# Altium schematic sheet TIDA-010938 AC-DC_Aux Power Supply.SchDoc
size 431 x 279 mm; Date: Not shown in title block; ApprovedBy: Not shown in title block; CheckedBy: Not shown in title block; Author: Not shown in title block; CompanyName: Not shown in title block; Engineer: Not shown in title block; Organization: Not shown in title block; Address1: Not shown in title block; Address2: Not shown in title block; Address3: Not shown in title block; Address4: Not shown in title block; DocumentNumber: 4; Revision: Use project parameter SCH_Rev; SheetNumber: 5; SheetTotal: 11; PageSetup: Record=PageOptions¦CenterHorizontal=True¦CenterVertical=True¦PrintScale=1.00¦XCorrection=1.00¦YCorrection=1.00¦PrintKind=0¦BorderSize=5000000¦LeftOffset=0¦BottomOffset=0¦Orientation=2¦PaperLength=1000¦PaperWidth=1000¦Scale=100¦PaperSource=15¦PrintQuality=600¦MediaType=1¦DitherType=10¦PaperKind=Letter¦PrintScaleMode=1
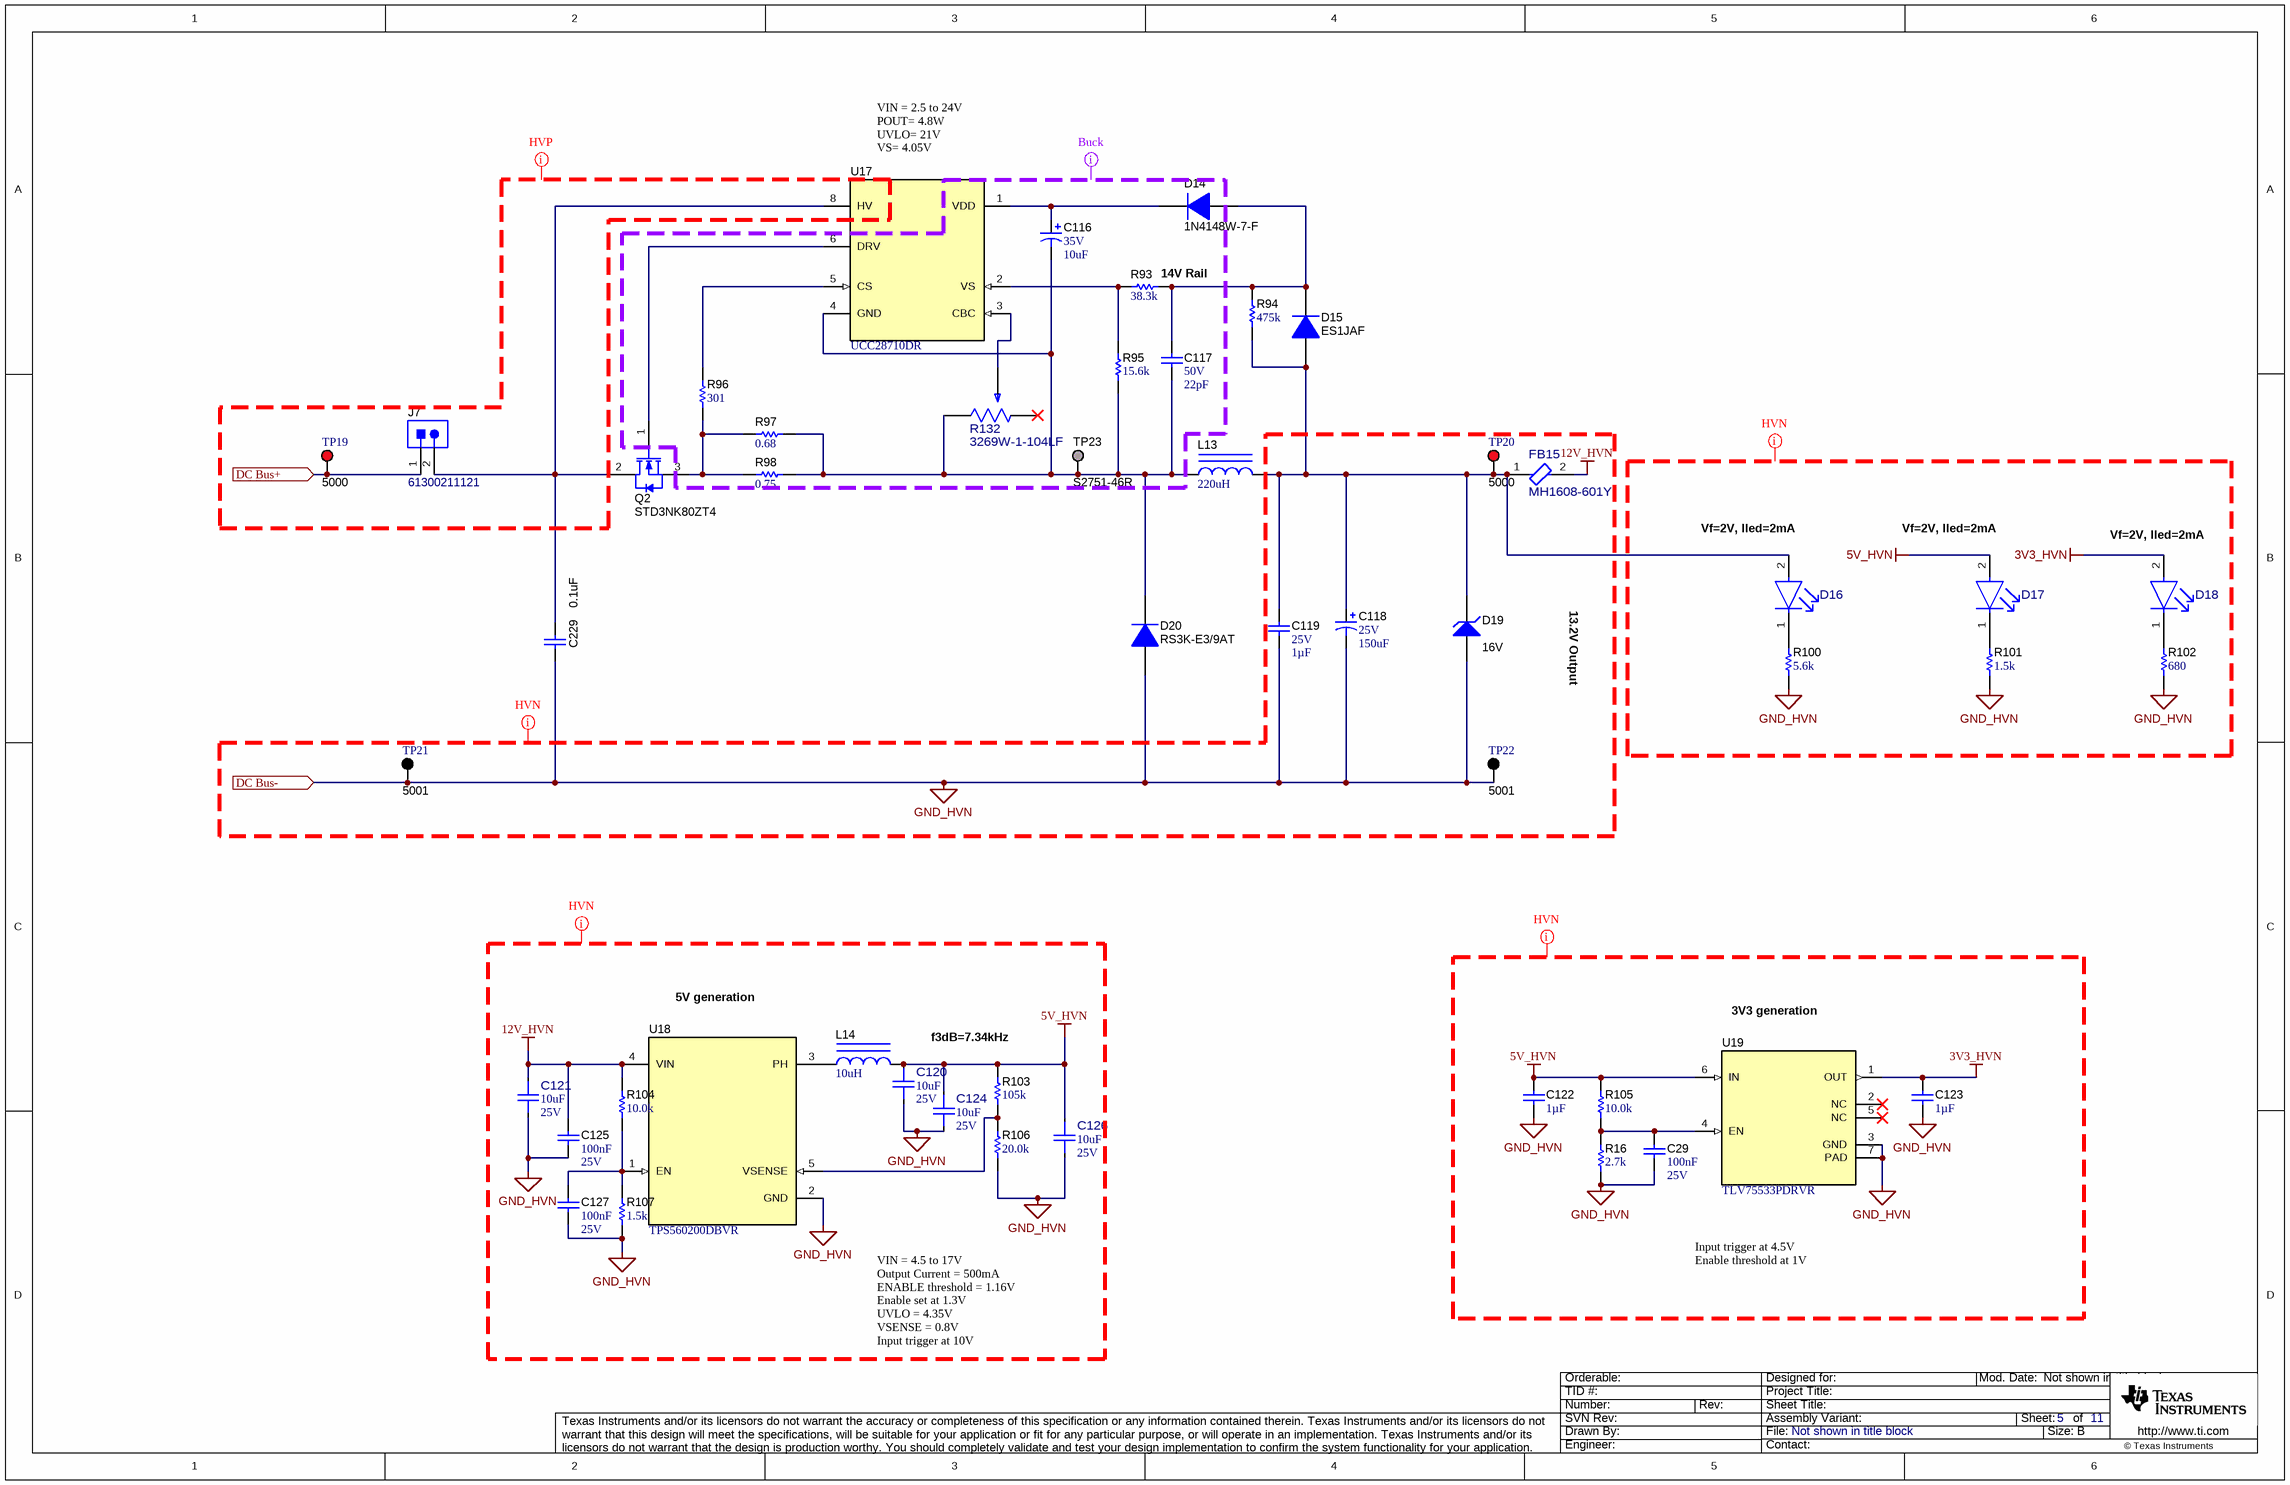
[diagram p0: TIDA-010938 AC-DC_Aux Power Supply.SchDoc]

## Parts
C29  Cap_F: 100nF  VDC_V: 25V  [0603]  (hidden comment: 06033C104JAT2A)
C116  VDC_V: 35V  ValueDisplayed: 10uF  [CAPPR2-5x11]  (hidden comment: UVR1V100MDD1TA)
C117  VDC_V: 50V  ValueDisplayed: 22pF  [0603]  (hidden comment: 06035A220JAT2A)
C118  VDC_V: 25V  ValueDisplayed: 150uF  [FR_630X1120]  (hidden comment: EEU-FR1E151B)
C119  VDC_V: 25V  ValueDisplayed: 1µF  [0603]  (hidden comment: TMK107BJ105KA-T)
C120  ValueDisplayed: 10uF  VDC_V: 25V  [FP-ZRB18AR61E106ME01L_0603-MFG]  (hidden comment: ZRB18AR61E106ME01L)
C121  ValueDisplayed: 10uF  VDC_V: 25V  [FP-ZRB18AR61E106ME01L_0603-MFG]  (hidden comment: ZRB18AR61E106ME01L)
C122  Cap_F: 1µF  [0603]  (hidden comment: 885012206026)
C123  Cap_F: 1µF  [0603]  (hidden comment: 885012206026)
C124  ValueDisplayed: 10uF  VDC_V: 25V  [FP-ZRB18AR61E106ME01L_0603-MFG]  (hidden comment: ZRB18AR61E106ME01L)
C125  Cap_F: 100nF  VDC_V: 25V  [0603]  (hidden comment: 06033C104JAT2A)
C126  ValueDisplayed: 10uF  VDC_V: 25V  [FP-ZRB18AR61E106ME01L_0603-MFG]  (hidden comment: ZRB18AR61E106ME01L)
C127  Cap_F: 100nF  VDC_V: 25V  [0603]  (hidden comment: 06033C104JAT2A)
C229  ValueDisplayed: 0.1uF  [1812_254]  (hidden comment: C1812W104KDRACTU)
D14  1N4148W-7-F  [SOD-123]
D15  ES1JAF  [SMAF]
D16  KG DELLS1.22-JGKH-24  [FP-KG DELLS1.22-JGKH-24_0603-MFG]  (value not drawn)
D17  KG DELLS1.22-JGKH-24  [FP-KG DELLS1.22-JGKH-24_0603-MFG]  (value not drawn)
D18  KG DELLS1.22-JGKH-24  [FP-KG DELLS1.22-JGKH-24_0603-MFG]  (value not drawn)
D19  value 16V  [SOD-123]  (hidden comment: BZT52C16-7-F)
D20  RS3K-E3/9AT  [SMC]
FB15  MH1608-601Y  [FP-MH1608-601Y_0603-MFG]
J7  61300211121  [WURTH_61300211121]
L13  ValueDisplayed: 220uH  [MSS1210]  (hidden comment: MSS1210-224KE)
L14  ValueDisplayed: 10uH  [SRN3015]  (hidden comment: SRN3015-100M)
Q2  STD3NK80ZT4  [DPAK]
R16  ValueDisplayed: 2.7k  [0603]  (hidden comment: CRCW06032K70JNEA)
R93  ValueDisplayed: 38.3k  [0603]  (hidden comment: RT0603DRE0738K3L)
R94  ValueDisplayed: 475k  [1206]  (hidden comment: CRCW1206475KFKEA)
R95  ValueDisplayed: 15.6k  [0603]  (hidden comment: RT0603DRE0715K6L)
R96  ValueDisplayed: 301  [0603]  (hidden comment: RT0603DRE07301RL)
R97  ValueDisplayed: 0.68  [0805_HV]  (hidden comment: ERJ-6RQFR68V)
R98  ValueDisplayed: 0.75  [1206]  (hidden comment: CSR1206FKR750)
R100  ValueDisplayed: 5.6k  [0603]  (hidden comment: RC0603JR-075K6L)
R101  ValueDisplayed: 1.5k  [0603]  (hidden comment: ERJ-3GEYJ152V)
R102  ValueDisplayed: 680  [0603]  (hidden comment: RC0603JR-07680RL)
R103  ValueDisplayed: 105k  [0603]  (hidden comment: RT0603BRD07105KL)
R104  ValueDisplayed: 10.0k  [0603]  (hidden comment: RG1608P-103-B-T5)
R105  ValueDisplayed: 10.0k  [0603]  (hidden comment: RG1608P-103-B-T5)
R106  ValueDisplayed: 20.0k  [0603]  (hidden comment: RT0603DRE0720KL)
R107  ValueDisplayed: 1.5k  [0603]  (hidden comment: CRCW06031K50JNEA)
R132  3269W-1-104LF  [FP-3269W-1-104LF_SMD-MFG]
TP19  5000  [Keystone5000]
TP20  5000  [Keystone5000]
TP21  5001  [Keystone5001]
TP22  5001  [Keystone5001]
TP23  S2751-46R  [Harwin_S2751-46R]  (no BOM)
U17  UCC28710DR  [D0007A_N]
U18  TPS560200DBVR  [DBV0005A_N]
U19  TLV75533PDRVR  [DRV0006A]

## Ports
DC Bus+ (in), DC Bus- (in)

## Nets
3V3_HVN: C123.1 D18.2(ANODE) U19.1(OUT)
5V_HVN: C120.1 C122.1 C124.1 C126.1 D17.2(ANODE) L14.2 R103.1 R105.1 U19.6(IN)
12V_HVN: C121.1 C125.2 FB15.2 R104.1 U18.4(VIN)
GND_HVN: C29.1 C118.2(-) C119.2 C120.2 C121.2 C122.2 C123.2 C124.2 C125.1 C126.2 C127.1 C229.2 D19.2(A) D20.2(A) R16.1 R100.2 R101.1 R102.1 R106.2 R107.1 TP21.1 TP22.1 U18.2(GND) U19.3(GND) U19.7(PAD) ; port DC Bus-
DC Bus+: J7.1 TP19.1 ; port DC Bus+
NetC29_2: C29.2 R16.2 R105.2 U19.4(EN)
NetC116_1: C116.1(+) D14.1(K) U17.1(VDD)
NetC116_2: C116.2(-) C117.2 D20.1(K) L13.1 R95.1 R97.2 R98.2 R132.1(CCW) TP23.1 U17.4(GND)
NetC117_1: C117.1 D14.2(A) D15.1(K) R93.2 R94.1
NetC118_1: C118.1(+) C119.1 D15.2(A) D16.2(ANODE) D19.1(K) FB15.1 L13.2 R94.2 TP20.1
NetC127_2: C127.2 R104.2 R107.2 U18.1(EN)
NetC229_1: C229.1 J7.2 Q2.2(D) U17.8(HV)
NetD16_1: D16.1(CATHODE) R100.1
NetD17_1: D17.1(CATHODE) R101.2
NetD18_1: D18.1(CATHODE) R102.2
NetL14_1: L14.1 U18.3(PH)
NetQ2_1: Q2.1(G) U17.6(DRV)
NetQ2_3: Q2.3(S) R96.2 R97.1 R98.1
NetR93_1: R93.1 R95.2 U17.2(VS)
NetR96_1: R96.1 U17.5(CS)
NetR103_2: R103.2 R106.1 U18.5(VSENSE)
NetR132_2: R132.2(WIPER) U17.3(CBC)

Not connected (* = marked no-connect by the designer): R132 3(CW)*; U19 2(NC)* 5(NC)*

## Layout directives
net class HVN: 3V3_HVN, 5V_HVN, 12V_HVN, GND_HVN
net class Buck: (no net found under the mark)
net class HVP: (no net found under the mark)

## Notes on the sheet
- VIN = 2.5 to 24V
  POUT= 4.8W
  UVLO= 21V
  VS= 4.05V
- (near R93) 14V Rail
- (near D16) Vf=2V, Iled=2mA
- (near D17) Vf=2V, Iled=2mA
- (near D18) Vf=2V, Iled=2mA
- 13.2V Output
- 5V generation
- f3dB=7.34kHz
- 3V3 generation
- Input trigger at 4.5V
  Enable threshold at 1V
- VIN = 4.5 to 17V
  Output Current = 500mA
  ENABLE threshold = 1.16V
  Enable set at 1.3V
  UVLO = 4.35V
  VSENSE = 0.8V
  Input trigger at 10V

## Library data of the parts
C29 C125 C127 = CMP-0006752-5: CAP, CERM, 0.1 uF, 25 V, +/- 5%, X7R, 0603; Manufacturer: AVX; TaMin_C: -55°C; ESR_ohm: 0.05; Polarized: N; SizeAreaWB_mm2: 4.68; Value1: 0.05 ohm; U/M: EA; Value: 0.1uF; TaMax_C: 125°C; SizeZ_mm: 1; SizeX_mm: 1.6; SizeY_mm: 0.8; SizeArea_mm2: 1.28; AEC Category: Q200
C116 = CMP-0010555-2: CAP, AL, 10 uF, 35 V, +/- 20%, TH; Manufacturer: Nichicon; TaMin_C: -40°C; Polarized: Y; SizeAreaWB_mm2: 49; Value1: Unknown; U/M: EA; Value: 10uF; TaMax_C: 85°C; SizeZ_mm: 11; SizeX_mm: 5; Cap_Case: 5x11; SizeArea_mm2: 25; CompType: Capacitor; AEC Qualified: N; Cap_F: 10µF; AEC Category: Q200
C117 = CMP-0006775-4: CAP, CERM, 22 pF, 50 V, +/- 5%, C0G/NP0, 0603; Manufacturer: AVX; TaMin_C: -55°C; ESR_ohm: 2.59d; Polarized: N; SizeAreaWB_mm2: 4.68; Value1: 0.259 ohm; U/M: EA; Value: 22pF; TaMax_C: 125°C; SizeZ_mm: 1; SizeX_mm: 1.6; SizeY_mm: 0.8; SizeArea_mm2: 1.28; AEC Category: Q200
C118 = CMP-0010348-1: CAP, AL, 150 uF, 25 V, +/- 20%, TH; Manufacturer: Panasonic; TaMin_C: -40°C; Polarized: Y; SizeAreaWB_mm2: 68.89; Value1: Unknown; U/M: EA; Value: 150uF; TaMax_C: 105°C; SizeZ_mm: 11.2; SizeX_mm: 6.3; Cap_Case: 6.3x11.2mm; SizeArea_mm2: 39.69; CompType: Capacitor; AEC Qualified: N; Cap_F: 150µF; IRMS_A: 4.55dA; AEC Category: Q200
C119 = CMP-0086152-1: CAP, CERM, 1 µF, 25 V,+/- 10%, X5R, 0603; Manufacturer: Taiyo Yuden; SizeAreaWB_mm2: 4.68; SizeZ_mm: 1; U/M: EA; Green_REACh: Passed; Value: 1uF; AEC Qualified: N; TaMax_C: 85°C; Green_Lifecycle: Active; AEC Category: Q200; SizeArea_mm2: 1.28; TaMin_C: -55°C; SizeY_mm: 0.8; SizeX_mm: 1.6
C120 C121 C124 C126 = CMP-0094458-1: 10µF ±20% 25V Ceramic Capacitor X5R 0603 (1608 Metric); Manufacturer: Murata Electronics; SizeZ_mm: 1.2mm; AEC Qualified: No
C122 C123 = CMP-0064932-4: CAP, CERM, 1 uF, 10 V,+/- 10%, X7R, 0603; Manufacturer: Wurth Elektronik; TaMin_C: -55°C; Polarized: N; SizeAreaWB_mm2: 4.68; Value1: Unknown; U/M: EA; Value: 1uF; TaMax_C: 125°C; SizeZ_mm: 1; SizeX_mm: 1.6; SizeY_mm: 0.8; Value2: 10V; SizeArea_mm2: 1.28; AEC Category: Q200
C229 = CMP-0009326-2: CAP, CERM, 0.1 uF, 1000 V, +/- 10%, X7R, 1812; Manufacturer: Kemet; Polarized: N; Value: 0.1uF; U/M: EA; Cap_F: 100nF; Value1: Unknown; VDC_V: 1kV; Value2: 1000V; TaMin_C: -55°C; TaMax_C: 125°C; Cap_Case: 1812; AEC Category: Q200; SizeArea_mm2: 14.4; SizeAreaWB_mm2: 23.1; SizeX_mm: 4.5; SizeY_mm: 3.2; SizeZ_mm: 2.54
D14 = CMP-0029001-2: Diode, Ultrafast, 100 V, 0.15 A, SOD-123; Manufacturer: Diodes Inc.; SizeX_mm: 3.85; Value2: 1.25V; Green_REACh: Passed; TJmax_C: 150°C; AEC Category: Q101; SizeAreaWB_mm2: 13.095; Value: 100V; Green_Lifecycle: Active; SizeY_mm: 1.7; Value1: 0.15A; SizeArea_mm2: 6.545; Io_A: 150mA; SizeZ_mm: 1.35
D15 = CMP-0029162-2: Diode, Ultrafast, 600 V, 1 A, AEC-Q101, SMAF; Manufacturer: Fairchild Semiconductor; TJmax_C: 150°C; Green_Lifecycle: Not Set; Green_REACh: Incomplete; Value: 600V; SizeY_mm: 2.5; Io_A: 1A; AEC Category: Q101; SizeArea_mm2: 11.75; SizeX_mm: 4.7; AEC Qualified: Y; SizeZ_mm: 1; SizeAreaWB_mm2: 19.95; Value2: 1.7V
D16-D18 = CMP-0093310-1: Standard LEDs - SMD Green TOPLED E 1608; Manufacturer: Osram Opto; AEC Grade: Grade 2; LambdaP: 572nm; SizeZ_mm: 0.7mm; LuminousFlux_PhiV: 0.016-0.0295lm; Luminous Intensity: 4.5-9.7mcd; LambdaD: 570nm; Tjmax_C: 125°C; Angle: 120°; Led Orientation: Top View; Forward Current: 2mA; Vf_V: 1.8V; AEC Qualified: Yes; Vr_V: 12V
D19 = CMP-0005769-4: Diode, Zener, 16 V, 500 mW, AEC-Q101, SOD-123; Manufacturer: Diodes Inc.; SizeZ_mm: 1.35; AEC Qualified: Y; SizeX_mm: 3.85; AEC Category: Q101; Power_W: 500mW; SizeY_mm: 1.7; Value1: 0.5W; SizeAreaWB_mm2: 13.095; SizeArea_mm2: 6.545; RJA_CperW: 338
D20 = CMP-0076883-2: Diode, Switching, 800 V, 3 A, SMC; Manufacturer: Vishay-Semiconductor; Value1: 3A; SizeAreaWB_mm2: 83.2686; SizeZ_mm: 2.6; AEC Category: Q101; SizeX_mm: 8.13; TJmax_C: 150°C; Value2: 1.3V; Vr_V: 800V; SizeArea_mm2: 50.5686; RJC_CperW: 50.0; Green_REACh: Incomplete; SizeY_mm: 6.22; Value: 800V; Green_Lifecycle: Not Set
FB15 = CMP-0037505-1: 600 Ohms @ 100 MHz 1 Power, Signal Line Ferrite Bead 0603 (1608 Metric) 1A 200mOhm; Manufacturer: Bourns; DCR_ohm: 0.2; SizeZ_mm: 1mm; AEC Qualified: No; Impedance At Frequency: 600Ω @ 100MHz; Test Frequency: 100MHz; Tolerance_%: 25%
J7 = CMP-0054794-2: Header, 2.54 mm, 2x1, Gold, TH; Manufacturer: Wurth Elektronik; Green_Lifecycle: Active; Green_REACh: Passed; Cert_UL: Y; Gender: Male; Pitch_mm: 2.54; Row_Count: 1; Shrouded: N
L13 = CMP-0061866-2: Inductor, Shielded, Ferrite, 220 uH, 2.1 A, 0.216 ohm, SMD; Manufacturer: Coilcraft; Isat: 2.8A @ 30% inductance drop; Irms: 2.1A @ 40C rise; Green_Lifecycle: Not Set; DCR_ohm: 2.16d; Green_REACh: Incomplete; Value: 220uH; SizeAreaWB_mm2: 204.49; Imax_A: 2.1A; SizeZ_mm: 10; SizeX_mm: 12.3; SizeArea_mm2: 151.29; Ind_H: 220µH; AEC Category: Q200
L14 = CMP-0056744-1: Inductor, Drum Core, Ferrite, 10 uH, 0.88 A, 0.276 ohm, SMD; Manufacturer: Bourns; Isat: 0.88A @ 30% inductance drop; Irms: 1A @ 40C rise; Green_Lifecycle: Active; SizeAreaWB_mm2: 16; DCR_ohm: 2.76d; Green_REACh: Passed; Value: 10uH; Imax_A: 8.8dA; SizeZ_mm: 1.5; SizeX_mm: 3; Value2: 0.88A; SizeArea_mm2: 9; Ind_H: 10µH; AEC Category: Q200
Q2 = CMP-0001278-3: MOSFET, N-CH, 800 V, 2.5 A, DPAK; Manufacturer: STMicroelectronics; Alternate Manufacturer: None; SizeY_mm: 6.54; SizeZ_mm: 2.29; VdsMax_V: 800V; SizeX_mm: 9.91; AEC Qualified: N; SizeArea_mm2: 64.8114; IdsMax_A: 2.5A; Value: 800V; SizeAreaWB_mm2: 101.7114; Value2: 19 nC; QgTyp_nC: 19; ChMode: Enhancement; Vgs_V: 30V; AEC Category: Q101
R16 = CMP-0025771-4: RES, 2.7 k, 5%, 0.1 W, AEC-Q200 Grade 0, 0603; Manufacturer: Vishay-Dale; Power_W: 100mW; TempCo: 200 ppm/C; Value_Code: 2k70; Value: 2.7k; EIA_Code: E24; SizeX_mm: 1.6; SizeY_mm: 0.8; SizeZ_mm: 1; Value2: 0.1W; SizeArea_mm2: 1.28; AEC Qualified: Y; VDC_V: 75V; AEC Category: Q200; AEC Grade: 0
R93 = CMP-0025199-3: RES, 38.3 k, 0.5%, 0.1 W, 0603; Manufacturer: Yageo America; TempCo: 50 ppm/C; Value_Code: 38k3; Power_W: 100mW; U/M: EA; Value: 38.3k; EIA_Code: E192; SizeX_mm: 1.6; SizeY_mm: 0.8; SizeZ_mm: 1; Value2: 0.1W; SizeArea_mm2: 1.28; VDC_V: 75V; AEC Category: Q200
R94 = CMP-0017008-3: RES, 475 k, 1%, 0.25 W, AEC-Q200 Grade 0, 1206; Manufacturer: Vishay-Dale; Power_W: 250mW; TempCo: 100 ppm/C; Value: 475k; EIA_Code: E96; SizeX_mm: 3.2; SizeY_mm: 1.6; SizeZ_mm: 1.35; Value2: 0.25W; SizeArea_mm2: 5.12; AEC Qualified: Y; VDC_V: 200V; AEC Category: Q200; AEC Grade: 0
R95 = CMP-0024711-2: RES, 15.6 k, 0.5%, 0.1 W, 0603; Manufacturer: Yageo America; Power_W: 100mW; TempCo: 50 ppm/C; Value_Code: 15k6; U/M: EA; Value: 15.6k; EIA_Code: E192; SizeX_mm: 1.6; SizeY_mm: 0.8; SizeZ_mm: 1; Value2: 0.1W; SizeArea_mm2: 1.28; VDC_V: 75V; AEC Category: Q200
R96 = CMP-0025116-2: RES, 301, 0.5%, 0.1 W, 0603; Manufacturer: Yageo America; Power_W: 100mW; TempCo: 50 ppm/C; Value_Code: 301R; U/M: EA; Value: 301; EIA_Code: E192; SizeX_mm: 1.6; SizeY_mm: 0.8; SizeZ_mm: 1; Value2: 0.1W; SizeArea_mm2: 1.28; VDC_V: 75V; AEC Category: Q200
R97 = CMP-0021844-3: RES, 0.68, 1%, 0.125 W, AEC-Q200 Grade 0, 0805; Manufacturer: Panasonic; Power_W: 125mW; TempCo: 250 ppm/C; Value_Code: R680; Value: 0.68; EIA_Code: E96; SizeX_mm: 2; SizeY_mm: 1.25; SizeZ_mm: 1.45; Value2: 0.125W; SizeArea_mm2: 2.5; AEC Qualified: Y; AEC Category: Q200; AEC Grade: 0; SizeAreaWB_mm2: 6.75
R98 = CMP-0017271-2: RES, 0.75, 1%, 0.5 W, 1206; Manufacturer: Stackpole Electronics Inc; Power_W: 500mW; TempCo: 100 ppm/C; Value_Code: R750; U/M: EA; Value: 0.75; EIA_Code: E96; Res_ohm: 7.5d; SizeX_mm: 3.2; SizeY_mm: 1.6; SizeZ_mm: 1.35; Value2: 0.5W; SizeArea_mm2: 5.12; AEC Category: Q200
R100 = CMP-0025933-5: RES, 5.6 k, 5%, 0.1 W, 0603; Manufacturer: Yageo; Power_W: 100mW; TempCo: 100 ppm/C; Value_Code: 5k60; Value: 5.6k; EIA_Code: E24; SizeX_mm: 1.6; SizeY_mm: 0.8; SizeZ_mm: 1; Value2: 0.1W; SizeArea_mm2: 1.28; AEC Qualified: N; VDC_V: 75V; AEC Category: Q200; SizeAreaWB_mm2: 4.68
R101 = CMP-0025877-3: RES, 1.5 k, 5%, 0.1 W, AEC-Q200 Grade 0, 0603; Manufacturer: Panasonic; Power_W: 100mW; TempCo: 200 ppm/C; Value_Code: 1k50; U/M: EA; Value: 1.5k; EIA_Code: E24; SizeX_mm: 1.6; SizeY_mm: 0.8; SizeZ_mm: 1; Value2: 0.1W; SizeArea_mm2: 1.28; AEC Qualified: Y; VDC_V: 75V; AEC Grade: 0; AEC Category: Q200
R102 = CMP-0025936-5: RES, 680, 5%, 0.1 W, 0603; Manufacturer: Yageo; Power_W: 100mW; TempCo: 100 ppm/C; Value_Code: 680R; Value: 680; EIA_Code: E24; SizeX_mm: 1.6; SizeY_mm: 0.8; SizeZ_mm: 1; Value2: 0.1W; SizeArea_mm2: 1.28; AEC Qualified: N; VDC_V: 75V; AEC Category: Q200; SizeAreaWB_mm2: 4.68
R103 = CMP-0023638-3: RES, 105 k, 0.1%, 0.1 W, 0603; Manufacturer: Yageo America; Power_W: 100mW; TempCo: 25 ppm/C; U/M: EA; Value: 105k; EIA_Code: E192; SizeX_mm: 1.6; SizeY_mm: 0.8; SizeZ_mm: 1; Value2: 0.1W; SizeArea_mm2: 1.28; VDC_V: 75V; AEC Category: Q200
R104 R105 = CMP-0023404-1: RES, 10.0 k, 0.1%, 0.1 W, 0603; Manufacturer: Susumu Co Ltd; Power_W: 100mW; TempCo: 25 ppm/C; Value_Code: 10k0; U/M: EA; Value: 10.0k; EIA_Code: E192; Res_ohm: 10k; SizeX_mm: 1.6; SizeY_mm: 0.8; SizeZ_mm: 1; Value2: 0.1W; SizeArea_mm2: 1.28; VDC_V: 75V; AEC Category: Q200
R106 = CMP-0024922-3: RES, 20.0 k, 0.5%, 0.1 W, 0603; Manufacturer: Yageo America; Power_W: 100mW; TempCo: 50 ppm/C; Value_Code: 20k0; U/M: EA; Value: 20.0k; EIA_Code: E192; Res_ohm: 20k; SizeX_mm: 1.6; SizeY_mm: 0.8; SizeZ_mm: 1; Value2: 0.1W; SizeArea_mm2: 1.28; VDC_V: 75V; AEC Category: Q200
R107 = CMP-0025733-4: RES, 1.5 k, 5%, 0.1 W, AEC-Q200 Grade 0, 0603; Manufacturer: Vishay-Dale; Power_W: 100mW; TempCo: 200 ppm/C; Value_Code: 1k50; Value: 1.5k; EIA_Code: E24; SizeX_mm: 1.6; SizeY_mm: 0.8; SizeZ_mm: 1; Value2: 0.1W; SizeArea_mm2: 1.28; AEC Qualified: Y; VDC_V: 75V; AEC Category: Q200; AEC Grade: 0
R132 = CMP-0089217-1: 100 kOhms 0.25W, 1/4W Gull Wing Surface Mount Trimmer Potentiometer Cermet 12 Turn Top Adjustment; Manufacturer: Bourns; TempCo: 100ppm/°C; Tolerance_%: 10%; SizeZ_mm: 8.96mm; Res_ohm: 100k; AEC Qualified: No; Power_W: 250mW
TP19 TP20 = CMP-0055137-2: Test Point, Miniature, Red, TH; Manufacturer: Keystone Electronics; Green_REACh: Passed; Green_Lifecycle: Active; ContactFinish: Silver; CNHeader: FALSE; CT: TRUE
TP21 TP22 = CMP-0055138-2: Test Point, Miniature, Black, TH; Manufacturer: Keystone Electronics; ContactFinish: Silver; CNHeader: FALSE; Green_Lifecycle: Active; Green_REACh: Passed; CT: TRUE
TP23 = CMP-0003968-1: Test Point, SMT; Manufacturer: Harwin
U17 = CMP-0067230-2: Constant-Voltage, Constant-Current PWM Controller with Primary-Side Regulation, D0007A (SOIC-7); Alternate Manufacturer: Texas Instruments; SizeAreaWB_mm2: 55.2; U/M: EA; SizeZ_mm: 1.75; SizeX_mm: 6.0; SizeY_mm: 4.9; SizeArea_mm2: 29.4; CompType: IC; AEC Category: Q200; AEC Qualified: N
U18 = CMP-0067067-1: 17V Input, 500mA Synchronous Step-Down Regulator in SOT-23 with Advanced Eco-Mode(TM), DBV0005A (SOT-23-5); Alternate PartNumber: TPS560200DBVT; Alternate Manufacturer: Texas Instruments; Green_Lifecycle: Active; SizeAreaWB_mm2: 14.82; Green_REACh: Passed; U/M: EA; SizeZ_mm: 1.45; SizeX_mm: 2.8; SizeY_mm: 2.9; SizeArea_mm2: 8.12; CompType: IC
U19 = CMP-0013427-7: 500mA LDO, DRV0006A (WSON-6); Manufacturer: Texas Instruments; SizeX_mm: 2; CompType: IC; SizeZ_mm: 0.8; SizeArea_mm2: 4; SizeAreaWB_mm2: 9; U/M: EA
